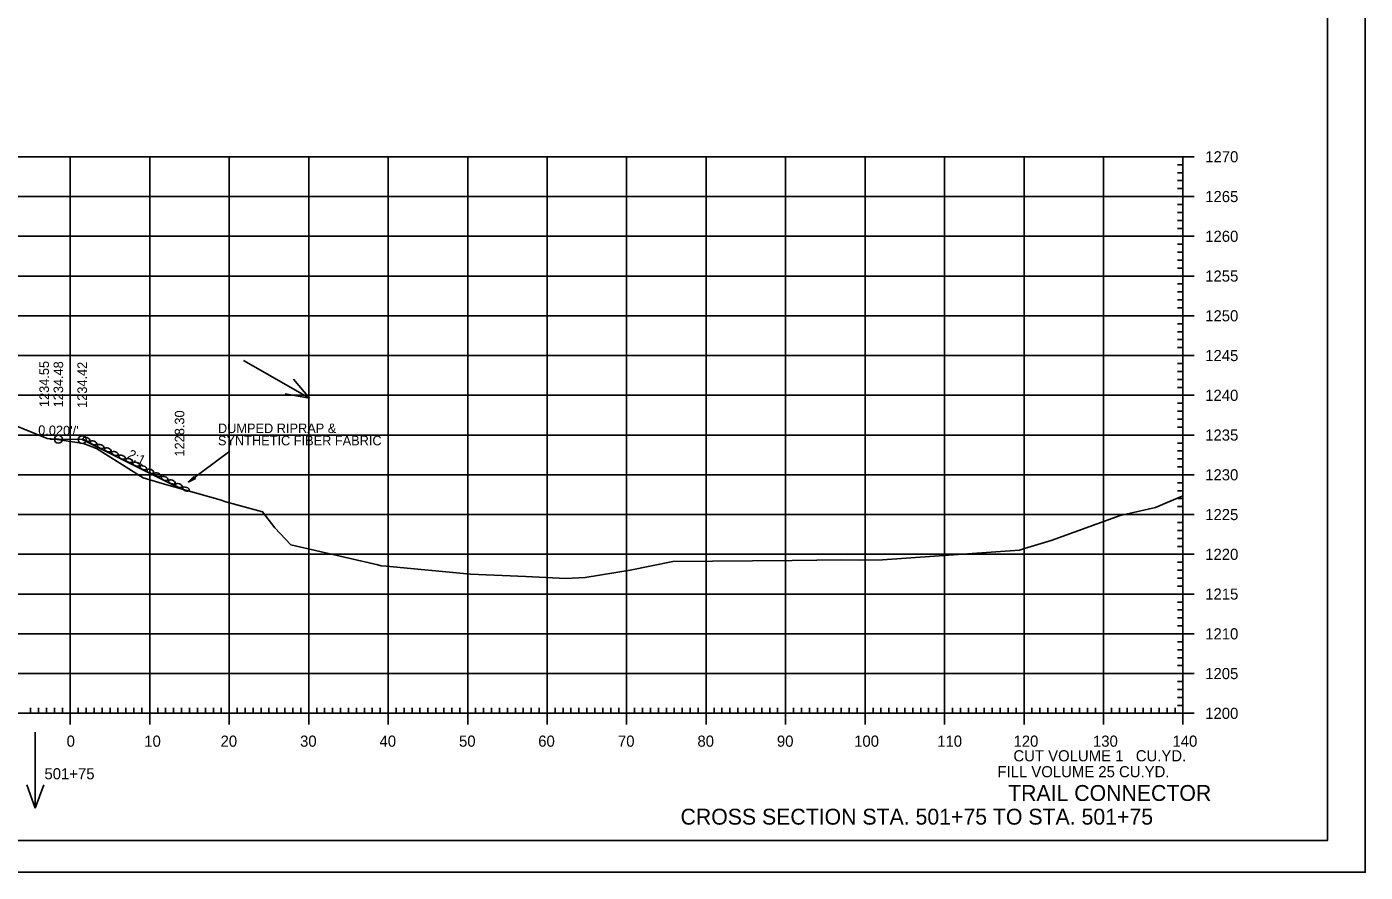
# Model space of a CAD drawing. Extents: x 1406028 to 1412453, y 321733 to 325986.
# Drawn here: x 1412284.8 to 1412453.2, y 322278.4 to 322384.7 of the extents above; entities that cross this region are included whole.
import ezdxf

# ---------------------------------------------------------------- set-up
doc = ezdxf.new("R2010")
doc.units = 0
for name, color, linetype in [('R_Axis', 7, 'Continuous'), ('R_Axis Annot', 7, 'Continuous'), ('R_Border', 7, 'Continuous'), ('R_Draft', 7, 'Continuous'), ('R_Exist Surface', 7, 'Continuous'), ('R_Fin Surface', 7, 'Continuous'), ('R_Fin Surface Annot', 7, 'Continuous'), ('R_Grid', 7, 'Continuous'), ('R_No Plot', 7, 'Continuous'), ('R_Water Annot', 7, 'Continuous')]:
    doc.layers.add(name, color=color, linetype=linetype)

msp = doc.modelspace()

# ---------------------------------------------------------------- linework, layer by layer
at = {"layer": 'R_Axis'}
for p, q in [((1412431.63, 322368.35), (1412428.83, 322368.35)), ((1412430.23, 322298.35), (1412430.23, 322368.35)), ((1412430.23, 322367.35), (1412429.53, 322367.35)), ((1412430.23, 322366.35), (1412429.53, 322366.35)), ((1412430.23, 322365.35), (1412429.53, 322365.35)), ((1412430.23, 322364.35), (1412429.53, 322364.35)), ((1412431.63, 322363.35), (1412428.83, 322363.35)), ((1412430.23, 322362.35), (1412429.53, 322362.35)), ((1412430.23, 322361.35), (1412429.53, 322361.35)), ((1412430.23, 322360.35), (1412429.53, 322360.35)), ((1412430.23, 322359.35), (1412429.53, 322359.35)), ((1412431.63, 322358.35), (1412428.83, 322358.35)), ((1412430.23, 322357.35), (1412429.53, 322357.35)), ((1412430.23, 322356.35), (1412429.53, 322356.35)), ((1412430.23, 322355.35), (1412429.53, 322355.35)), ((1412430.23, 322354.35), (1412429.53, 322354.35)), ((1412431.63, 322353.35), (1412428.83, 322353.35)), ((1412430.23, 322352.35), (1412429.53, 322352.35)), ((1412430.23, 322351.35), (1412429.53, 322351.35)), ((1412430.23, 322350.35), (1412429.53, 322350.35)), ((1412430.23, 322349.35), (1412429.53, 322349.35)), ((1412431.63, 322348.35), (1412428.83, 322348.35)), ((1412430.23, 322347.35), (1412429.53, 322347.35)), ((1412430.23, 322346.35), (1412429.53, 322346.35)), ((1412430.23, 322345.35), (1412429.53, 322345.35)), ((1412430.23, 322344.35), (1412429.53, 322344.35)), ((1412431.63, 322343.35), (1412428.83, 322343.35)), ((1412430.23, 322342.35), (1412429.53, 322342.35)), ((1412430.23, 322341.35), (1412429.53, 322341.35)), ((1412430.23, 322340.35), (1412429.53, 322340.35)), ((1412430.23, 322339.35), (1412429.53, 322339.35)), ((1412431.63, 322338.35), (1412428.83, 322338.35)), ((1412430.23, 322337.35), (1412429.53, 322337.35)), ((1412430.23, 322336.35), (1412429.53, 322336.35)), ((1412430.23, 322335.35), (1412429.53, 322335.35)), ((1412430.23, 322334.35), (1412429.53, 322334.35)), ((1412431.63, 322333.35), (1412428.83, 322333.35)), ((1412430.23, 322332.35), (1412429.53, 322332.35)), ((1412430.23, 322331.35), (1412429.53, 322331.35)), ((1412430.23, 322330.35), (1412429.53, 322330.35)), ((1412430.23, 322329.35), (1412429.53, 322329.35)), ((1412431.63, 322328.35), (1412428.83, 322328.35)), ((1412430.23, 322327.35), (1412429.53, 322327.35)), ((1412430.23, 322326.35), (1412429.53, 322326.35)), ((1412430.23, 322325.35), (1412429.53, 322325.35)), ((1412430.23, 322324.35), (1412429.53, 322324.35)), ((1412431.63, 322323.35), (1412428.83, 322323.35)), ((1412430.23, 322322.35), (1412429.53, 322322.35)), ((1412430.23, 322321.35), (1412429.53, 322321.35)), ((1412430.23, 322320.35), (1412429.53, 322320.35)), ((1412430.23, 322319.35), (1412429.53, 322319.35)), ((1412431.63, 322318.35), (1412428.83, 322318.35)), ((1412430.23, 322317.35), (1412429.53, 322317.35)), ((1412430.23, 322316.35), (1412429.53, 322316.35)), ((1412430.23, 322315.35), (1412429.53, 322315.35)), ((1412430.23, 322314.35), (1412429.53, 322314.35)), ((1412431.63, 322313.35), (1412428.83, 322313.35)), ((1412430.23, 322312.35), (1412429.53, 322312.35)), ((1412430.23, 322311.35), (1412429.53, 322311.35)), ((1412430.23, 322310.35), (1412429.53, 322310.35)), ((1412430.23, 322309.35), (1412429.53, 322309.35)), ((1412431.63, 322308.35), (1412428.83, 322308.35)), ((1412430.23, 322307.35), (1412429.53, 322307.35)), ((1412430.23, 322306.35), (1412429.53, 322306.35)), ((1412430.23, 322305.35), (1412429.53, 322305.35)), ((1412430.23, 322304.35), (1412429.53, 322304.35)), ((1412431.63, 322303.35), (1412428.83, 322303.35)), ((1412430.23, 322302.35), (1412429.53, 322302.35)), ((1412430.23, 322301.35), (1412429.53, 322301.35)), ((1412430.23, 322300.35), (1412429.53, 322300.35)), ((1412285.23, 322298.35), (1412285.23, 322299.05)), ((1412286.23, 322298.35), (1412286.23, 322299.05)), ((1412287.23, 322298.35), (1412287.23, 322299.05)), ((1412288.23, 322298.35), (1412288.23, 322299.05)), ((1412289.23, 322298.35), (1412289.23, 322299.05)), ((1412290.23, 322296.95), (1412290.23, 322299.75)), ((1412291.23, 322298.35), (1412291.23, 322299.05)), ((1412292.23, 322298.35), (1412292.23, 322299.05)), ((1412293.23, 322298.35), (1412293.23, 322299.05)), ((1412294.23, 322298.35), (1412294.23, 322299.05)), ((1412295.23, 322298.35), (1412295.23, 322299.05)), ((1412296.23, 322298.35), (1412296.23, 322299.05)), ((1412297.23, 322298.35), (1412297.23, 322299.05)), ((1412298.23, 322298.35), (1412298.23, 322299.05)), ((1412299.23, 322298.35), (1412299.23, 322299.05)), ((1412300.23, 322296.95), (1412300.23, 322299.75)), ((1412301.23, 322298.35), (1412301.23, 322299.05)), ((1412302.23, 322298.35), (1412302.23, 322299.05)), ((1412303.23, 322298.35), (1412303.23, 322299.05)), ((1412304.23, 322298.35), (1412304.23, 322299.05)), ((1412305.23, 322298.35), (1412305.23, 322299.05)), ((1412306.23, 322298.35), (1412306.23, 322299.05)), ((1412307.23, 322298.35), (1412307.23, 322299.05)), ((1412308.23, 322298.35), (1412308.23, 322299.05)), ((1412309.23, 322298.35), (1412309.23, 322299.05)), ((1412310.23, 322296.95), (1412310.23, 322299.75)), ((1412311.23, 322298.35), (1412311.23, 322299.05)), ((1412312.23, 322298.35), (1412312.23, 322299.05)), ((1412313.23, 322298.35), (1412313.23, 322299.05)), ((1412314.23, 322298.35), (1412314.23, 322299.05)), ((1412315.23, 322298.35), (1412315.23, 322299.05)), ((1412316.23, 322298.35), (1412316.23, 322299.05)), ((1412317.23, 322298.35), (1412317.23, 322299.05)), ((1412318.23, 322298.35), (1412318.23, 322299.05)), ((1412319.23, 322298.35), (1412319.23, 322299.05)), ((1412320.23, 322296.95), (1412320.23, 322299.75)), ((1412321.23, 322298.35), (1412321.23, 322299.05)), ((1412322.23, 322298.35), (1412322.23, 322299.05)), ((1412323.23, 322298.35), (1412323.23, 322299.05)), ((1412324.23, 322298.35), (1412324.23, 322299.05)), ((1412325.23, 322298.35), (1412325.23, 322299.05)), ((1412326.23, 322298.35), (1412326.23, 322299.05)), ((1412327.23, 322298.35), (1412327.23, 322299.05)), ((1412328.23, 322298.35), (1412328.23, 322299.05)), ((1412329.23, 322298.35), (1412329.23, 322299.05)), ((1412330.23, 322296.95), (1412330.23, 322299.75)), ((1412331.23, 322298.35), (1412331.23, 322299.05)), ((1412332.23, 322298.35), (1412332.23, 322299.05)), ((1412333.23, 322298.35), (1412333.23, 322299.05)), ((1412334.23, 322298.35), (1412334.23, 322299.05)), ((1412335.23, 322298.35), (1412335.23, 322299.05)), ((1412336.23, 322298.35), (1412336.23, 322299.05)), ((1412337.23, 322298.35), (1412337.23, 322299.05)), ((1412338.23, 322298.35), (1412338.23, 322299.05)), ((1412339.23, 322298.35), (1412339.23, 322299.05)), ((1412340.23, 322296.95), (1412340.23, 322299.75)), ((1412341.23, 322298.35), (1412341.23, 322299.05)), ((1412342.23, 322298.35), (1412342.23, 322299.05)), ((1412343.23, 322298.35), (1412343.23, 322299.05)), ((1412344.23, 322298.35), (1412344.23, 322299.05)), ((1412345.23, 322298.35), (1412345.23, 322299.05)), ((1412346.23, 322298.35), (1412346.23, 322299.05)), ((1412347.23, 322298.35), (1412347.23, 322299.05)), ((1412348.23, 322298.35), (1412348.23, 322299.05)), ((1412349.23, 322298.35), (1412349.23, 322299.05)), ((1412350.23, 322296.95), (1412350.23, 322299.75)), ((1412351.23, 322298.35), (1412351.23, 322299.05)), ((1412352.23, 322298.35), (1412352.23, 322299.05)), ((1412353.23, 322298.35), (1412353.23, 322299.05)), ((1412354.23, 322298.35), (1412354.23, 322299.05)), ((1412355.23, 322298.35), (1412355.23, 322299.05)), ((1412356.23, 322298.35), (1412356.23, 322299.05)), ((1412357.23, 322298.35), (1412357.23, 322299.05)), ((1412358.23, 322298.35), (1412358.23, 322299.05)), ((1412359.23, 322298.35), (1412359.23, 322299.05)), ((1412360.23, 322296.95), (1412360.23, 322299.75)), ((1412361.23, 322298.35), (1412361.23, 322299.05)), ((1412362.23, 322298.35), (1412362.23, 322299.05)), ((1412363.23, 322298.35), (1412363.23, 322299.05)), ((1412364.23, 322298.35), (1412364.23, 322299.05)), ((1412365.23, 322298.35), (1412365.23, 322299.05)), ((1412366.23, 322298.35), (1412366.23, 322299.05)), ((1412367.23, 322298.35), (1412367.23, 322299.05)), ((1412368.23, 322298.35), (1412368.23, 322299.05)), ((1412369.23, 322298.35), (1412369.23, 322299.05)), ((1412370.23, 322296.95), (1412370.23, 322299.75)), ((1412371.23, 322298.35), (1412371.23, 322299.05)), ((1412372.23, 322298.35), (1412372.23, 322299.05)), ((1412373.23, 322298.35), (1412373.23, 322299.05)), ((1412374.23, 322298.35), (1412374.23, 322299.05)), ((1412375.23, 322298.35), (1412375.23, 322299.05)), ((1412376.23, 322298.35), (1412376.23, 322299.05)), ((1412377.23, 322298.35), (1412377.23, 322299.05)), ((1412378.23, 322298.35), (1412378.23, 322299.05)), ((1412379.23, 322298.35), (1412379.23, 322299.05)), ((1412380.23, 322296.95), (1412380.23, 322299.75)), ((1412381.23, 322298.35), (1412381.23, 322299.05)), ((1412382.23, 322298.35), (1412382.23, 322299.05)), ((1412383.23, 322298.35), (1412383.23, 322299.05)), ((1412384.23, 322298.35), (1412384.23, 322299.05)), ((1412385.23, 322298.35), (1412385.23, 322299.05)), ((1412386.23, 322298.35), (1412386.23, 322299.05)), ((1412387.23, 322298.35), (1412387.23, 322299.05)), ((1412388.23, 322298.35), (1412388.23, 322299.05)), ((1412389.23, 322298.35), (1412389.23, 322299.05)), ((1412390.23, 322296.95), (1412390.23, 322299.75)), ((1412391.23, 322298.35), (1412391.23, 322299.05)), ((1412392.23, 322298.35), (1412392.23, 322299.05)), ((1412393.23, 322298.35), (1412393.23, 322299.05)), ((1412394.23, 322298.35), (1412394.23, 322299.05)), ((1412395.23, 322298.35), (1412395.23, 322299.05)), ((1412396.23, 322298.35), (1412396.23, 322299.05)), ((1412397.23, 322298.35), (1412397.23, 322299.05)), ((1412398.23, 322298.35), (1412398.23, 322299.05)), ((1412399.23, 322298.35), (1412399.23, 322299.05)), ((1412400.23, 322296.95), (1412400.23, 322299.75)), ((1412401.23, 322298.35), (1412401.23, 322299.05)), ((1412402.23, 322298.35), (1412402.23, 322299.05)), ((1412403.23, 322298.35), (1412403.23, 322299.05)), ((1412404.23, 322298.35), (1412404.23, 322299.05)), ((1412405.23, 322298.35), (1412405.23, 322299.05)), ((1412406.23, 322298.35), (1412406.23, 322299.05)), ((1412407.23, 322298.35), (1412407.23, 322299.05)), ((1412408.23, 322298.35), (1412408.23, 322299.05)), ((1412409.23, 322298.35), (1412409.23, 322299.05)), ((1412410.23, 322296.95), (1412410.23, 322299.75)), ((1412411.23, 322298.35), (1412411.23, 322299.05)), ((1412412.23, 322298.35), (1412412.23, 322299.05)), ((1412413.23, 322298.35), (1412413.23, 322299.05)), ((1412414.23, 322298.35), (1412414.23, 322299.05)), ((1412415.23, 322298.35), (1412415.23, 322299.05)), ((1412416.23, 322298.35), (1412416.23, 322299.05)), ((1412417.23, 322298.35), (1412417.23, 322299.05)), ((1412418.23, 322298.35), (1412418.23, 322299.05)), ((1412419.23, 322298.35), (1412419.23, 322299.05)), ((1412420.23, 322296.95), (1412420.23, 322299.75)), ((1412421.23, 322298.35), (1412421.23, 322299.05)), ((1412422.23, 322298.35), (1412422.23, 322299.05)), ((1412423.23, 322298.35), (1412423.23, 322299.05)), ((1412424.23, 322298.35), (1412424.23, 322299.05)), ((1412425.23, 322298.35), (1412425.23, 322299.05)), ((1412426.23, 322298.35), (1412426.23, 322299.05)), ((1412427.23, 322298.35), (1412427.23, 322299.05)), ((1412428.23, 322298.35), (1412428.23, 322299.05)), ((1412429.23, 322298.35), (1412429.23, 322299.05)), ((1412430.23, 322299.35), (1412429.53, 322299.35)), ((1412430.23, 322296.95), (1412430.23, 322299.75)), ((1412150.23, 322298.35), (1412430.23, 322298.35)), ((1412431.63, 322298.35), (1412428.83, 322298.35))]:
    msp.add_line(p, q, dxfattribs=at)
at = {"layer": 'R_Border'}
for q in [(1412448.41, 322487.81), (1412132.23, 322282.35)]:
    msp.add_line((1412448.41, 322282.35), q, dxfattribs=at)
at = {"layer": 'R_Draft'}
for p, q in [((1412310.31, 322331.33), (1412305.07, 322327.41)), ((1412305.79, 322328.13), (1412305.07, 322327.41)), ((1412305.97, 322327.89), (1412305.07, 322327.41)), ((1412305.8, 322328.11), (1412305.21, 322327.51)), ((1412305.95, 322327.91), (1412305.21, 322327.51)), ((1412305.82, 322328.09), (1412305.35, 322327.62)), ((1412305.93, 322327.93), (1412305.35, 322327.62)), ((1412305.83, 322328.07), (1412305.48, 322327.71)), ((1412305.92, 322327.95), (1412305.48, 322327.71)), ((1412305.85, 322328.05), (1412305.62, 322327.82)), ((1412305.9, 322327.97), (1412305.62, 322327.82)), ((1412305.86, 322328.03), (1412305.75, 322327.92)), ((1412305.89, 322327.99), (1412305.75, 322327.92)), ((1412305.79, 322328.13), (1412305.97, 322327.89))]:
    msp.add_line(p, q, dxfattribs=at)
for centre in [(1412292.26, 322332.82), (1412293.16, 322332.37), (1412294.05, 322331.92), (1412294.95, 322331.48), (1412295.84, 322331.03), (1412296.73, 322330.58), (1412297.63, 322330.14), (1412298.52, 322329.69), (1412299.42, 322329.24), (1412300.31, 322328.79), (1412301.21, 322328.35), (1412302.1, 322327.9), (1412303, 322327.45), (1412303.89, 322327), (1412304.78, 322326.56)]:
    msp.add_ellipse(centre, major_axis=(0.409, -0.156), ratio=0.517889, dxfattribs=at)
at = {"layer": 'R_Exist Surface'}
msp.add_lwpolyline([(1412282.89, 322334.7), (1412287.33, 322332.93), (1412288.31, 322332.82), (1412291.88, 322332.29), (1412293.52, 322331.64), (1412299.39, 322327.98), (1412301.79, 322327.27), (1412309.08, 322325.2), (1412309.78, 322324.96), (1412314.42, 322323.69), (1412315.96, 322321.7), (1412317.98, 322319.56), (1412328.93, 322317.03), (1412329.35, 322316.91), (1412329.97, 322316.85), (1412340.6, 322315.85), (1412347.54, 322315.56), (1412352.58, 322315.3), (1412355.02, 322315.45), (1412360.67, 322316.35), (1412366.04, 322317.43), (1412381.05, 322317.58), (1412387.26, 322317.64), (1412389.61, 322317.62), (1412392.42, 322317.66), (1412409.65, 322318.87), (1412410.3, 322319.1), (1412413.66, 322320.07), (1412422.34, 322323.22), (1412426.79, 322324.24), (1412430.23, 322325.7)], dxfattribs=at)
at = {"layer": 'R_Fin Surface'}
msp.add_lwpolyline([(1412287.65, 322332.89), (1412287.73, 322332.85), (1412288.73, 322332.83), (1412291.73, 322332.77), (1412292.73, 322332.27), (1412303.98, 322326.65)], dxfattribs=at)
at = {"layer": 'R_Grid'}
for p, q in [((1412150.23, 322368.35), (1412430.23, 322368.35)), ((1412290.23, 322298.35), (1412290.23, 322368.35)), ((1412300.23, 322298.35), (1412300.23, 322368.35)), ((1412310.23, 322298.35), (1412310.23, 322368.35)), ((1412320.23, 322298.35), (1412320.23, 322368.35)), ((1412330.23, 322298.35), (1412330.23, 322368.35)), ((1412340.23, 322298.35), (1412340.23, 322368.35)), ((1412350.23, 322298.35), (1412350.23, 322368.35)), ((1412360.23, 322298.35), (1412360.23, 322368.35)), ((1412370.23, 322298.35), (1412370.23, 322368.35)), ((1412380.23, 322298.35), (1412380.23, 322368.35)), ((1412390.23, 322298.35), (1412390.23, 322368.35)), ((1412400.23, 322298.35), (1412400.23, 322368.35)), ((1412410.23, 322298.35), (1412410.23, 322368.35)), ((1412420.23, 322298.35), (1412420.23, 322368.35)), ((1412430.23, 322298.35), (1412430.23, 322368.35)), ((1412150.23, 322363.35), (1412430.23, 322363.35)), ((1412150.23, 322358.35), (1412430.23, 322358.35)), ((1412150.23, 322353.35), (1412430.23, 322353.35)), ((1412150.23, 322348.35), (1412430.23, 322348.35)), ((1412150.23, 322343.35), (1412430.23, 322343.35)), ((1412150.23, 322338.35), (1412430.23, 322338.35)), ((1412150.23, 322333.35), (1412430.23, 322333.35)), ((1412150.23, 322328.35), (1412430.23, 322328.35)), ((1412150.23, 322323.35), (1412430.23, 322323.35)), ((1412150.23, 322318.35), (1412430.23, 322318.35)), ((1412150.23, 322313.35), (1412430.23, 322313.35)), ((1412150.23, 322308.35), (1412430.23, 322308.35)), ((1412150.23, 322303.35), (1412430.23, 322303.35)), ((1412150.23, 322298.35), (1412430.23, 322298.35))]:
    msp.add_line(p, q, dxfattribs=at)
at = {"layer": 'R_No Plot'}
msp.add_line((1412119.83, 322278.37), (1412453.16, 322278.37), dxfattribs=at)
for points in [[(1412119.82, 322491.7), (1412453.16, 322491.7), (1412453.16, 322278.36), (1412119.82, 322278.36)], [(1412366.15, 322487.81), (1412385.77, 322487.81), (1412385.77, 322477.93), (1412401.88, 322477.93), (1412425.08, 322477.93), (1412425.2, 322449.77), (1412448.41, 322449.77), (1412448.41, 322282.35), (1412132.23, 322282.35), (1412132.23, 322487.81)]]:
    msp.add_lwpolyline(points, close=True, dxfattribs=at)
for centre in [(1412288.73, 322332.83), (1412291.73, 322332.77)]:
    msp.add_circle(centre, 0.5, dxfattribs=at)
at = {"layer": 'R_Water Annot'}
for p, q in [((1412312.01, 322342.73), (1412320.33, 322338)), ((1412320.33, 322338), (1412318.31, 322340.37)), ((1412320.33, 322338), (1412317.26, 322338.52)), ((1412285.82, 322295.99), (1412285.82, 322286.42)), ((1412285.82, 322286.42), (1412284.76, 322289.35)), ((1412285.82, 322286.42), (1412286.89, 322289.35))]:
    msp.add_line(p, q, dxfattribs=at)

# ---------------------------------------------------------------- texts
at = {"layer": 'R_Axis Annot'}
for s, p in [('1270', (1412433.03, 322367.65)), ('1265', (1412433.03, 322362.65)), ('1260', (1412433.03, 322357.65)), ('1255', (1412433.03, 322352.65)), ('1250', (1412433.03, 322347.65)), ('1245', (1412433.03, 322342.65)), ('1240', (1412433.03, 322337.65)), ('1235', (1412433.03, 322332.65)), ('1230', (1412433.03, 322327.65)), ('1225', (1412433.03, 322322.65)), ('1220', (1412433.03, 322317.65)), ('1215', (1412433.03, 322312.65)), ('1210', (1412433.03, 322307.65)), ('1205', (1412433.03, 322302.65)), ('1200', (1412433.03, 322297.65)), ('0', (1412289.77, 322294.15)), ('10', (1412299.54, 322294.15)), ('20', (1412309.14, 322294.15)), ('30', (1412319.14, 322294.15)), ('40', (1412329.14, 322294.15)), ('50', (1412339.14, 322294.15)), ('60', (1412349.11, 322294.15)), ('70', (1412359.14, 322294.15)), ('80', (1412369.14, 322294.15)), ('90', (1412379.14, 322294.15)), ('100', (1412388.86, 322294.15)), ('110', (1412399.31, 322294.15)), ('120', (1412408.91, 322294.15)), ('130', (1412418.91, 322294.15)), ('140', (1412428.91, 322294.15)), ('CUT VOLUME 1   CU.YD.', (1412408.9, 322292.31)), ('FILL VOLUME 25 CU.YD.', (1412406.89, 322290.31)), ('501+75', (1412286.98, 322290.05))]:
    msp.add_text(s, height=1.4, dxfattribs=at).set_placement(p)
at = {"layer": 'R_Draft'}
for s, height, p in [('DUMPED RIPRAP &', 1.2, (1412308.81, 322333.6)), ('SYNTHETIC FIBER FABRIC', 1.2, (1412308.81, 322332.06)), ('TRAIL CONNECTOR', 2, (1412408.23, 322287.33)), ('CROSS SECTION STA. 501+75 TO STA. 501+75', 2, (1412367.01, 322284.35))]:
    msp.add_text(s, height=height, dxfattribs=at).set_placement(p)
at = {"layer": 'R_Fin Surface Annot'}
for s, rotation, p in [('1234.55', 90, (1412287.55, 322336.87)), ('1234.48', 90, (1412289.33, 322336.83)), ('1234.42', 90, (1412292.33, 322336.77)), ('1228.30', 90, (1412304.58, 322330.65)), ("0.020'/'", 358.8542, (1412286.18, 322333.38)), ('2:1', 333.4349, (1412297.33, 322330.53))]:
    msp.add_text(s, height=1.2, rotation=rotation, dxfattribs=at).set_placement(p)

doc.saveas('drawing.dxf')
